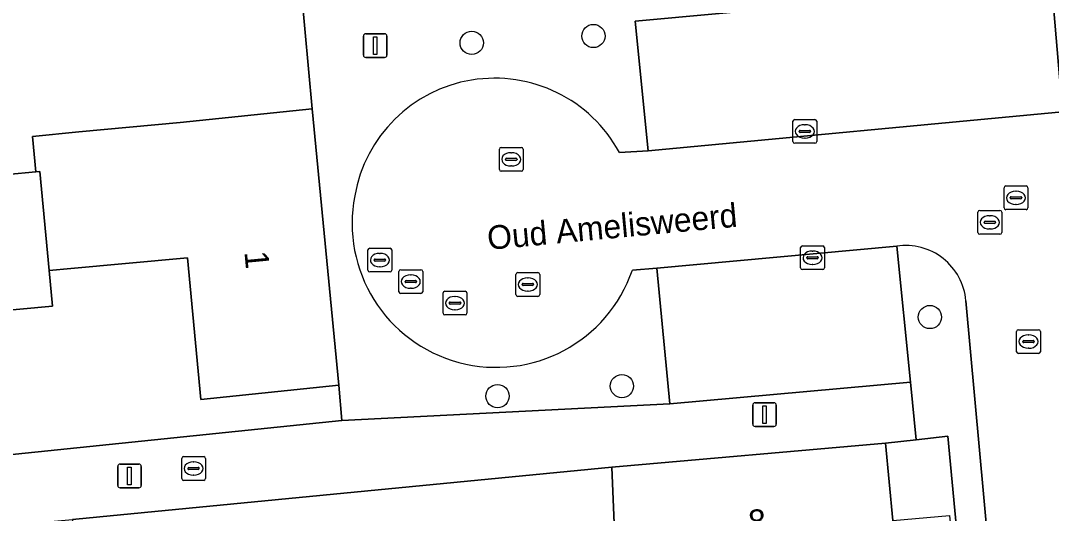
# Model space of a CAD drawing. Extents: x 157793 to 159380, y 380877 to 382313.
# Drawn here: x 158390.06 to 158433.42, y 381212.96 to 381233.72 of the extents above; entities that cross this region are included whole.
import ezdxf

# ---------------------------------------------------------------- set-up
doc = ezdxf.new("R2010")
doc.units = 0
for name, color, linetype in [('IMGEO_Boom', 7, 'Continuous'), ('IMGEO_Erf', 7, 'Continuous'), ('IMGEO_Kolk', 7, 'Continuous'), ('IMGEO_Lichtmast', 7, 'Continuous'), ('IMGEO_Openbare_ruimte_label', 7, 'Continuous'), ('IMGEO_Pand', 7, 'Continuous'), ('IMGEO_Pand_nummerreeks', 7, 'Continuous'), ('IMGEO_Parkeervlak_open', 7, 'Continuous'), ('IMGEO_Rijbaan_lokaal_open', 7, 'Continuous'), ('IMGEO_Rioolput', 7, 'Continuous'), ('IMGEO_Voetpad_open', 7, 'Continuous')]:
    doc.layers.add(name, color=color, linetype=linetype)

msp = doc.modelspace()

# ---------------------------------------------------------------- linework, layer by layer
at = {"layer": 'IMGEO_Boom'}
for centre in [(158414.154, 381233.068), (158409.036, 381232.779), (158428.309, 381221.233), (158415.353, 381218.326), (158410.121, 381217.902)]:
    msp.add_circle(centre, 0.489, dxfattribs=at)
at = {"layer": 'IMGEO_Erf'}
msp.add_lwpolyline([(158383.543, 381226.677), (158390.701, 381227.35), (158390.56, 381228.843), (158392.511, 381229.026), (158396.772, 381229.427), (158402.322, 381229.995), (158401.867, 381235.072), (158409.933, 381235.822), (158434.485, 381238.106)], dxfattribs=at)
for points in [[(158391.263, 381223.189), (158391.401, 381221.697), (158385.588, 381221.157), (158386.141, 381215.192), (158386.294, 381215.09), (158403.568, 381216.879), (158403.446, 381218.363), (158397.636, 381217.766), (158397.081, 381223.729), (158392.024, 381223.26), (158391.414, 381223.203)], [(158426.971, 381210.23), (158420.985, 381209.671), (158421.515, 381203.992), (158430.122, 381204.888), (158429.061, 381216.213), (158427.728, 381216.063), (158426.439, 381215.918), (158426.744, 381212.658), (158429.138, 381212.882), (158429.457, 381209.47), (158427.063, 381209.246)], [(158414.936, 381214.906), (158392.379, 381212.725), (158392.251, 381212.713), (158392.373, 381211.219), (158392.521, 381211.233), (158394.742, 381211.443), (158403.775, 381212.297), (158403.911, 381210.806), (158405.635, 381210.969), (158415.056, 381211.859)]]:
    msp.add_lwpolyline(points, close=True, dxfattribs=at)
at = {"layer": 'IMGEO_Kolk'}
for p, q in [((158422.621, 381229.552), (158423.473, 381229.552)), ((158422.546, 381228.626), (158422.546, 381229.478)), ((158423.034, 381229.332), (158423.059, 381229.332)), ((158423.547, 381229.478), (158423.547, 381228.626)), ((158422.805, 381229.046), (158422.805, 381229.058)), ((158423.243, 381229.009), (158422.845, 381229.009)), ((158422.848, 381229.095), (158423.246, 381229.095)), ((158423.057, 381228.772), (158423.032, 381228.772)), ((158423.289, 381229.058), (158423.289, 381229.046)), ((158410.199, 381227.448), (158410.199, 381228.3)), ((158410.274, 381228.374), (158411.126, 381228.374)), ((158411.2, 381228.3), (158411.2, 381227.448)), ((158423.473, 381228.552), (158422.621, 381228.552)), ((158410.458, 381227.868), (158410.458, 381227.88)), ((158410.896, 381227.831), (158410.498, 381227.831)), ((158410.501, 381227.917), (158410.899, 381227.917)), ((158410.687, 381228.154), (158410.712, 381228.154)), ((158410.942, 381227.88), (158410.942, 381227.868)), ((158410.71, 381227.594), (158410.685, 381227.594)), ((158411.126, 381227.374), (158410.274, 381227.374)), ((158422.871, 381223.305), (158422.871, 381224.157)), ((158422.946, 381224.231), (158423.798, 381224.231)), ((158423.359, 381224.011), (158423.384, 381224.011)), ((158423.872, 381224.157), (158423.872, 381223.305)), ((158423.13, 381223.725), (158423.13, 381223.737)), ((158423.568, 381223.688), (158423.17, 381223.688)), ((158423.173, 381223.774), (158423.571, 381223.774)), ((158423.614, 381223.737), (158423.614, 381223.725)), ((158410.972, 381223.105), (158411.824, 381223.105)), ((158423.798, 381223.231), (158422.946, 381223.231)), ((158423.382, 381223.451), (158423.357, 381223.451)), ((158410.897, 381222.179), (158410.897, 381223.031)), ((158411.199, 381222.648), (158411.597, 381222.648)), ((158411.385, 381222.885), (158411.41, 381222.885)), ((158411.898, 381223.031), (158411.898, 381222.179)), ((158411.156, 381222.599), (158411.156, 381222.611)), ((158411.594, 381222.562), (158411.196, 381222.562)), ((158411.408, 381222.325), (158411.383, 381222.325)), ((158411.64, 381222.611), (158411.64, 381222.599)), ((158411.824, 381222.105), (158410.972, 381222.105)), ((158431.955, 381219.773), (158431.955, 381220.625)), ((158432.03, 381220.699), (158432.882, 381220.699)), ((158432.443, 381220.479), (158432.468, 381220.479)), ((158432.956, 381220.625), (158432.956, 381219.773)), ((158432.214, 381220.193), (158432.214, 381220.205)), ((158432.652, 381220.156), (158432.254, 381220.156)), ((158432.257, 381220.242), (158432.655, 381220.242)), ((158432.698, 381220.205), (158432.698, 381220.193)), ((158432.882, 381219.699), (158432.03, 381219.699)), ((158432.466, 381219.919), (158432.441, 381219.919)), ((158396.837, 381214.428), (158396.837, 381215.28)), ((158396.912, 381215.354), (158397.764, 381215.354)), ((158397.838, 381215.28), (158397.838, 381214.428)), ((158397.096, 381214.848), (158397.096, 381214.86)), ((158397.139, 381214.897), (158397.537, 381214.897)), ((158397.325, 381215.134), (158397.35, 381215.134)), ((158397.58, 381214.86), (158397.58, 381214.848)), ((158397.534, 381214.811), (158397.136, 381214.811)), ((158397.348, 381214.574), (158397.323, 381214.574)), ((158397.764, 381214.354), (158396.912, 381214.354))]:
    msp.add_line(p, q, dxfattribs=at)
for points in [[(158422.621, 381229.552), (158423.473, 381229.552)], [(158422.546, 381228.626), (158422.546, 381229.478)], [(158423.547, 381229.478), (158423.547, 381228.626)], [(158410.199, 381227.448), (158410.199, 381228.3)], [(158410.274, 381228.374), (158411.126, 381228.374)], [(158411.2, 381228.3), (158411.2, 381227.448)], [(158423.473, 381228.552), (158422.621, 381228.552)], [(158411.126, 381227.374), (158410.274, 381227.374)], [(158422.871, 381223.305), (158422.871, 381224.157)], [(158422.946, 381224.231), (158423.798, 381224.231)], [(158423.872, 381224.157), (158423.872, 381223.305)], [(158410.972, 381223.105), (158411.824, 381223.105)], [(158423.798, 381223.231), (158422.946, 381223.231)], [(158410.897, 381222.179), (158410.897, 381223.031)], [(158411.898, 381223.031), (158411.898, 381222.179)], [(158411.824, 381222.105), (158410.972, 381222.105)], [(158431.955, 381219.773), (158431.955, 381220.625)], [(158432.03, 381220.699), (158432.882, 381220.699)], [(158432.956, 381220.625), (158432.956, 381219.773)], [(158432.882, 381219.699), (158432.03, 381219.699)], [(158396.837, 381214.428), (158396.837, 381215.28)], [(158396.912, 381215.354), (158397.764, 381215.354)], [(158397.838, 381215.28), (158397.838, 381214.428)], [(158397.764, 381214.354), (158396.912, 381214.354)]]:
    msp.add_lwpolyline(points, dxfattribs=at)
for centre, radius, start, end in [((158422.623, 381229.476), 0.0765, 91.552, 178.448), ((158422.623, 381229.476), 0.0765, 91.552, 178.448), ((158423.471, 381229.476), 0.0765, 1.552, 88.448), ((158423.471, 381229.476), 0.0765, 1.552, 88.448), ((158422.845, 381229.055), 0.0403, 85.8775, 175.7526), ((158422.842, 381229.045), 0.0366, 178.938, 274.7102), ((158423.246, 381229.052), 0.043, 264.8664, 352.4533), ((158423.25, 381229.057), 0.0386, 1.7309, 96.639), ((158410.276, 381228.298), 0.0765, 91.552, 178.448), ((158410.276, 381228.298), 0.0765, 91.552, 178.448), ((158411.124, 381228.298), 0.0765, 1.552, 88.448), ((158411.124, 381228.298), 0.0765, 1.552, 88.448), ((158422.623, 381228.628), 0.0765, 181.552, 268.448), ((158422.623, 381228.628), 0.0765, 181.552, 268.448), ((158423.471, 381228.628), 0.0765, 271.552, 358.448), ((158423.471, 381228.628), 0.0765, 271.552, 358.448), ((158410.498, 381227.877), 0.0403, 85.8775, 175.7526), ((158410.495, 381227.867), 0.0366, 178.938, 274.7102), ((158410.899, 381227.874), 0.043, 264.8664, 352.4533), ((158410.903, 381227.879), 0.0386, 1.7309, 96.639), ((158410.276, 381227.45), 0.0765, 181.552, 268.448), ((158410.276, 381227.45), 0.0765, 181.552, 268.448), ((158411.124, 381227.45), 0.0765, 271.552, 358.448), ((158411.124, 381227.45), 0.0765, 271.552, 358.448), ((158422.948, 381224.155), 0.0765, 91.552, 178.448), ((158422.948, 381224.155), 0.0765, 91.552, 178.448), ((158423.796, 381224.155), 0.0765, 1.552, 88.448), ((158423.796, 381224.155), 0.0765, 1.552, 88.448), ((158423.17, 381223.734), 0.0403, 85.8775, 175.7526), ((158423.167, 381223.724), 0.0366, 178.938, 274.7102), ((158423.571, 381223.731), 0.043, 264.8664, 352.4533), ((158423.575, 381223.736), 0.0386, 1.7309, 96.639), ((158410.974, 381223.029), 0.0765, 91.552, 178.448), ((158410.974, 381223.029), 0.0765, 91.552, 178.448), ((158411.822, 381223.029), 0.0765, 1.552, 88.448), ((158411.822, 381223.029), 0.0765, 1.552, 88.448), ((158422.948, 381223.307), 0.0765, 181.552, 268.448), ((158422.948, 381223.307), 0.0765, 181.552, 268.448), ((158423.796, 381223.307), 0.0765, 271.552, 358.448), ((158423.796, 381223.307), 0.0765, 271.552, 358.448), ((158411.196, 381222.608), 0.0403, 85.8775, 175.7526), ((158411.601, 381222.61), 0.0386, 1.7309, 96.639), ((158411.193, 381222.598), 0.0366, 178.938, 274.7102), ((158411.597, 381222.605), 0.043, 264.8664, 352.4533), ((158410.974, 381222.181), 0.0765, 181.552, 268.448), ((158410.974, 381222.181), 0.0765, 181.552, 268.448), ((158411.822, 381222.181), 0.0765, 271.552, 358.448), ((158411.822, 381222.181), 0.0765, 271.552, 358.448), ((158432.032, 381220.623), 0.0765, 91.552, 178.448), ((158432.032, 381220.623), 0.0765, 91.552, 178.448), ((158432.88, 381220.623), 0.0765, 1.552, 88.448), ((158432.88, 381220.623), 0.0765, 1.552, 88.448), ((158432.254, 381220.202), 0.0403, 85.8775, 175.7526), ((158432.251, 381220.192), 0.0366, 178.938, 274.7102), ((158432.655, 381220.199), 0.043, 264.8664, 352.4533), ((158432.659, 381220.204), 0.0386, 1.7309, 96.639), ((158432.032, 381219.775), 0.0765, 181.552, 268.448), ((158432.032, 381219.775), 0.0765, 181.552, 268.448), ((158432.88, 381219.775), 0.0765, 271.552, 358.448), ((158432.88, 381219.775), 0.0765, 271.552, 358.448), ((158396.914, 381215.278), 0.0765, 91.552, 178.448), ((158396.914, 381215.278), 0.0765, 91.552, 178.448), ((158397.762, 381215.278), 0.0765, 1.552, 88.448), ((158397.762, 381215.278), 0.0765, 1.552, 88.448), ((158397.136, 381214.857), 0.0403, 85.8775, 175.7526), ((158397.133, 381214.847), 0.0366, 178.938, 274.7102), ((158397.537, 381214.854), 0.043, 264.8664, 352.4533), ((158397.541, 381214.859), 0.0386, 1.7309, 96.639), ((158396.914, 381214.43), 0.0765, 181.552, 268.448), ((158396.914, 381214.43), 0.0765, 181.552, 268.448), ((158397.762, 381214.43), 0.0765, 271.552, 358.448), ((158397.762, 381214.43), 0.0765, 271.552, 358.448)]:
    msp.add_arc(centre, radius, start, end, dxfattribs=at)
for centre, major_axis, ratio, start_param, end_param in [((158423.033, 381229.052), (-0.387, 0.002), 0.722429, 4.712389, 7.853982), ((158423.058, 381229.052), (-0.39, 0.002), 0.717154, 1.570796, 4.712389), ((158410.686, 381227.874), (-0.387, 0.002), 0.722429, 4.712389, 7.853982), ((158410.711, 381227.874), (-0.39, 0.002), 0.717154, 1.570796, 4.712389), ((158423.358, 381223.731), (-0.387, 0.002), 0.722429, 4.712389, 7.853982), ((158423.383, 381223.731), (-0.39, 0.002), 0.717154, 1.570796, 4.712389), ((158411.384, 381222.605), (-0.387, 0.002), 0.722429, 4.712389, 7.853982), ((158411.409, 381222.605), (-0.39, 0.002), 0.717154, 1.570796, 4.712389), ((158432.442, 381220.199), (-0.387, 0.002), 0.722429, 4.712389, 7.853982), ((158432.467, 381220.199), (-0.39, 0.002), 0.717154, 1.570796, 4.712389), ((158397.324, 381214.854), (-0.387, 0.002), 0.722429, 4.712389, 7.853982), ((158397.349, 381214.854), (-0.39, 0.002), 0.717154, 1.570796, 4.712389)]:
    msp.add_ellipse(centre, major_axis=major_axis, ratio=ratio, start_param=start_param, end_param=end_param, dxfattribs=at)
at = {"layer": 'IMGEO_Lichtmast'}
for p, q in [((158404.48, 381232.264), (158404.48, 381233.064)), ((158404.48, 381233.064), (158404.48, 381232.264)), ((158404.58, 381233.164), (158405.37, 381233.164)), ((158405.37, 381233.164), (158404.58, 381233.164)), ((158405.47, 381233.064), (158405.47, 381232.264)), ((158405.47, 381232.264), (158405.47, 381233.064)), ((158405.37, 381232.164), (158404.58, 381232.164)), ((158404.58, 381232.164), (158405.37, 381232.164)), ((158420.856, 381216.724), (158420.856, 381217.524)), ((158420.856, 381217.524), (158420.856, 381216.724)), ((158420.956, 381217.624), (158421.746, 381217.624)), ((158421.746, 381217.624), (158420.956, 381217.624)), ((158421.846, 381217.524), (158421.846, 381216.724)), ((158421.846, 381216.724), (158421.846, 381217.524)), ((158421.746, 381216.624), (158420.956, 381216.624)), ((158420.956, 381216.624), (158421.746, 381216.624)), ((158394.145, 381214.14), (158394.145, 381214.94)), ((158394.145, 381214.94), (158394.145, 381214.14)), ((158394.245, 381215.04), (158395.035, 381215.04)), ((158395.035, 381215.04), (158394.245, 381215.04)), ((158395.135, 381214.94), (158395.135, 381214.14)), ((158395.135, 381214.14), (158395.135, 381214.94)), ((158395.035, 381214.04), (158394.245, 381214.04)), ((158394.245, 381214.04), (158395.035, 381214.04))]:
    msp.add_line(p, q, dxfattribs=at)
for points in [[(158404.9, 381233.039), (158405.05, 381233.039), (158405.05, 381232.289), (158404.9, 381232.289), (158404.9, 381233.039)], [(158421.276, 381217.499), (158421.426, 381217.499), (158421.426, 381216.749), (158421.276, 381216.749), (158421.276, 381217.499)], [(158394.565, 381214.915), (158394.715, 381214.915), (158394.715, 381214.165), (158394.565, 381214.165), (158394.565, 381214.915)]]:
    msp.add_lwpolyline(points, dxfattribs=at)
for centre, start, end in [((158404.58, 381233.064), 90, 180), ((158404.58, 381233.064), 90, 180), ((158405.37, 381233.064), 0, 90), ((158405.37, 381233.064), 360, 90), ((158404.58, 381232.264), 180, 270), ((158404.58, 381232.264), 180, 270), ((158405.37, 381232.264), 270, 0), ((158405.37, 381232.264), 270, 0), ((158420.956, 381217.524), 90, 180), ((158420.956, 381217.524), 90, 180), ((158421.746, 381217.524), 0, 90), ((158421.746, 381217.524), 360, 90), ((158420.956, 381216.724), 180, 270), ((158420.956, 381216.724), 180, 270), ((158421.746, 381216.724), 270, 0), ((158421.746, 381216.724), 270, 0), ((158394.245, 381214.94), 90, 180), ((158394.245, 381214.94), 90, 180), ((158395.035, 381214.94), 0, 90), ((158395.035, 381214.94), 360, 90), ((158394.245, 381214.14), 180, 270), ((158394.245, 381214.14), 180, 270), ((158395.035, 381214.14), 270, 0), ((158395.035, 381214.14), 270, 0)]:
    msp.add_arc(centre, 0.1, start, end, dxfattribs=at)
at = {"layer": 'IMGEO_Pand'}
for points in [[(158402.322, 381229.995), (158396.772, 381229.427), (158392.511, 381229.026), (158390.56, 381228.843), (158390.701, 381227.35), (158390.876, 381227.366), (158391.263, 381223.189), (158391.414, 381223.203), (158392.024, 381223.26), (158397.081, 381223.729), (158397.636, 381217.766), (158403.446, 381218.363)], [(158390.701, 381227.35), (158383.543, 381226.677), (158383.555, 381226.549), (158379.381, 381226.167), (158379.397, 381225.995), (158379.573, 381224.131), (158380.47, 381214.66), (158386.141, 381215.192), (158385.588, 381221.157), (158391.401, 381221.697), (158391.263, 381223.189), (158390.876, 381227.366)], [(158426.971, 381210.23), (158426.744, 381212.658), (158426.439, 381215.918), (158414.936, 381214.906), (158415.056, 381211.859), (158416.047, 381203.193), (158416.207, 381203.208), (158418.385, 381203.408), (158418.369, 381203.587), (158421.525, 381203.881), (158421.515, 381203.992), (158420.985, 381209.671)]]:
    msp.add_lwpolyline(points, close=True, dxfattribs=at)
at = {"layer": 'IMGEO_Parkeervlak_open'}
for points in [[(158434.025, 381229.887), (158433.976, 381230.217), (158433.857, 381230.192), (158433.421, 381235.303), (158415.915, 381233.688), (158416.46, 381228.231)], [(158427.485, 381218.497), (158426.913, 381224.222), (158416.824, 381223.289), (158417.373, 381217.577)]]:
    msp.add_lwpolyline(points, close=True, dxfattribs=at)
at = {"layer": 'IMGEO_Rijbaan_lokaal_open'}
for points in [[(158434.025, 381229.887), (158416.46, 381228.231), (158415.248, 381228.166)], [(158429.819, 381221.92), (158431.533, 381203.205), (158436.443, 381203.658), (158434.025, 381229.887)], [(158415.796, 381223.213), (158416.824, 381223.289), (158426.913, 381224.222)]]:
    msp.add_lwpolyline(points, dxfattribs=at)
for centre, radius, start, end in [((158410, 381225.322), 5.969, 28.4562, 170.1794), ((158410.064, 381225.173), 6.058, 168.8941, 341.1228), ((158427.283, 381221.703), 2.546, 4.8817, 98.3489)]:
    msp.add_arc(centre, radius, start, end, dxfattribs=at)
at = {"layer": 'IMGEO_Rioolput'}
for p, q in [((158431.427, 381225.829), (158431.427, 381226.681)), ((158431.502, 381226.755), (158432.354, 381226.755)), ((158431.915, 381226.535), (158431.94, 381226.535)), ((158432.428, 381226.681), (158432.428, 381225.829)), ((158431.686, 381226.249), (158431.686, 381226.261)), ((158432.124, 381226.212), (158431.726, 381226.212)), ((158431.729, 381226.298), (158432.127, 381226.298)), ((158432.17, 381226.261), (158432.17, 381226.249)), ((158430.403, 381225.721), (158431.255, 381225.721)), ((158432.354, 381225.755), (158431.502, 381225.755)), ((158431.938, 381225.975), (158431.913, 381225.975)), ((158430.328, 381224.795), (158430.328, 381225.647)), ((158430.587, 381225.215), (158430.587, 381225.227)), ((158430.63, 381225.264), (158431.028, 381225.264)), ((158430.816, 381225.501), (158430.841, 381225.501)), ((158431.071, 381225.227), (158431.071, 381225.215)), ((158431.329, 381225.647), (158431.329, 381224.795)), ((158431.025, 381225.178), (158430.627, 381225.178)), ((158430.839, 381224.941), (158430.814, 381224.941)), ((158431.255, 381224.721), (158430.403, 381224.721)), ((158404.673, 381223.207), (158404.673, 381224.059)), ((158404.748, 381224.133), (158405.6, 381224.133)), ((158405.674, 381224.059), (158405.674, 381223.207)), ((158404.932, 381223.627), (158404.932, 381223.639)), ((158405.37, 381223.59), (158404.972, 381223.59)), ((158404.975, 381223.676), (158405.373, 381223.676)), ((158405.161, 381223.913), (158405.186, 381223.913)), ((158405.416, 381223.639), (158405.416, 381223.627)), ((158405.6, 381223.133), (158404.748, 381223.133)), ((158405.184, 381223.353), (158405.159, 381223.353)), ((158405.973, 381222.298), (158405.973, 381223.15)), ((158406.048, 381223.224), (158406.9, 381223.224)), ((158406.974, 381223.15), (158406.974, 381222.298)), ((158406.232, 381222.718), (158406.232, 381222.73)), ((158406.67, 381222.681), (158406.272, 381222.681)), ((158406.275, 381222.767), (158406.673, 381222.767)), ((158406.461, 381223.004), (158406.486, 381223.004)), ((158406.716, 381222.73), (158406.716, 381222.718)), ((158406.9, 381222.224), (158406.048, 381222.224)), ((158406.484, 381222.444), (158406.459, 381222.444)), ((158407.833, 381221.394), (158407.833, 381222.246)), ((158407.908, 381222.32), (158408.76, 381222.32)), ((158408.834, 381222.246), (158408.834, 381221.394)), ((158408.092, 381221.814), (158408.092, 381221.826)), ((158408.53, 381221.777), (158408.132, 381221.777)), ((158408.135, 381221.863), (158408.533, 381221.863)), ((158408.321, 381222.1), (158408.346, 381222.1)), ((158408.576, 381221.826), (158408.576, 381221.814)), ((158408.76, 381221.32), (158407.908, 381221.32)), ((158408.344, 381221.54), (158408.319, 381221.54))]:
    msp.add_line(p, q, dxfattribs=at)
for points in [[(158431.427, 381225.829), (158431.427, 381226.681)], [(158431.502, 381226.755), (158432.354, 381226.755)], [(158432.428, 381226.681), (158432.428, 381225.829)], [(158430.403, 381225.721), (158431.255, 381225.721)], [(158432.354, 381225.755), (158431.502, 381225.755)], [(158430.328, 381224.795), (158430.328, 381225.647)], [(158431.329, 381225.647), (158431.329, 381224.795)], [(158431.255, 381224.721), (158430.403, 381224.721)], [(158404.673, 381223.207), (158404.673, 381224.059)], [(158404.748, 381224.133), (158405.6, 381224.133)], [(158405.674, 381224.059), (158405.674, 381223.207)], [(158405.6, 381223.133), (158404.748, 381223.133)], [(158405.973, 381222.298), (158405.973, 381223.15)], [(158406.048, 381223.224), (158406.9, 381223.224)], [(158406.974, 381223.15), (158406.974, 381222.298)], [(158406.9, 381222.224), (158406.048, 381222.224)], [(158407.833, 381221.394), (158407.833, 381222.246)], [(158407.908, 381222.32), (158408.76, 381222.32)], [(158408.834, 381222.246), (158408.834, 381221.394)], [(158408.76, 381221.32), (158407.908, 381221.32)]]:
    msp.add_lwpolyline(points, dxfattribs=at)
for centre, radius, start, end in [((158431.504, 381226.679), 0.0765, 91.552, 178.448), ((158431.504, 381226.679), 0.0765, 91.552, 178.448), ((158432.352, 381226.679), 0.0765, 1.552, 88.448), ((158432.352, 381226.679), 0.0765, 1.552, 88.448), ((158431.726, 381226.258), 0.0403, 85.8775, 175.7526), ((158431.723, 381226.248), 0.0366, 178.938, 274.7102), ((158432.127, 381226.255), 0.043, 264.8664, 352.4533), ((158432.131, 381226.26), 0.0386, 1.7309, 96.639), ((158430.405, 381225.645), 0.0765, 91.552, 178.448), ((158430.405, 381225.645), 0.0765, 91.552, 178.448), ((158431.253, 381225.645), 0.0765, 1.552, 88.448), ((158431.253, 381225.645), 0.0765, 1.552, 88.448), ((158431.504, 381225.831), 0.0765, 181.552, 268.448), ((158431.504, 381225.831), 0.0765, 181.552, 268.448), ((158432.352, 381225.831), 0.0765, 271.552, 358.448), ((158432.352, 381225.831), 0.0765, 271.552, 358.448), ((158430.627, 381225.224), 0.0403, 85.8775, 175.7526), ((158431.032, 381225.226), 0.0386, 1.7309, 96.639), ((158430.405, 381224.797), 0.0765, 181.552, 268.448), ((158430.405, 381224.797), 0.0765, 181.552, 268.448), ((158430.624, 381225.214), 0.0366, 178.938, 274.7102), ((158431.028, 381225.221), 0.043, 264.8664, 352.4533), ((158431.253, 381224.797), 0.0765, 271.552, 358.448), ((158431.253, 381224.797), 0.0765, 271.552, 358.448), ((158404.75, 381224.057), 0.0765, 91.552, 178.448), ((158404.75, 381224.057), 0.0765, 91.552, 178.448), ((158405.598, 381224.057), 0.0765, 1.552, 88.448), ((158405.598, 381224.057), 0.0765, 1.552, 88.448), ((158404.972, 381223.636), 0.0403, 85.8775, 175.7526), ((158404.969, 381223.626), 0.0366, 178.938, 274.7102), ((158405.373, 381223.633), 0.043, 264.8664, 352.4533), ((158405.377, 381223.638), 0.0386, 1.7309, 96.639), ((158404.75, 381223.209), 0.0765, 181.552, 268.448), ((158404.75, 381223.209), 0.0765, 181.552, 268.448), ((158405.598, 381223.209), 0.0765, 271.552, 358.448), ((158405.598, 381223.209), 0.0765, 271.552, 358.448), ((158406.05, 381223.148), 0.0765, 91.552, 178.448), ((158406.05, 381223.148), 0.0765, 91.552, 178.448), ((158406.898, 381223.148), 0.0765, 1.552, 88.448), ((158406.898, 381223.148), 0.0765, 1.552, 88.448), ((158406.272, 381222.727), 0.0403, 85.8775, 175.7526), ((158406.269, 381222.717), 0.0366, 178.938, 274.7102), ((158406.673, 381222.724), 0.043, 264.8664, 352.4533), ((158406.677, 381222.729), 0.0386, 1.7309, 96.639), ((158406.05, 381222.3), 0.0765, 181.552, 268.448), ((158406.05, 381222.3), 0.0765, 181.552, 268.448), ((158406.898, 381222.3), 0.0765, 271.552, 358.448), ((158406.898, 381222.3), 0.0765, 271.552, 358.448), ((158407.91, 381222.244), 0.0765, 91.552, 178.448), ((158407.91, 381222.244), 0.0765, 91.552, 178.448), ((158408.758, 381222.244), 0.0765, 1.552, 88.448), ((158408.758, 381222.244), 0.0765, 1.552, 88.448), ((158408.132, 381221.823), 0.0403, 85.8775, 175.7526), ((158408.129, 381221.813), 0.0366, 178.938, 274.7102), ((158408.533, 381221.82), 0.043, 264.8664, 352.4533), ((158408.537, 381221.825), 0.0386, 1.7309, 96.639), ((158407.91, 381221.396), 0.0765, 181.552, 268.448), ((158407.91, 381221.396), 0.0765, 181.552, 268.448), ((158408.758, 381221.396), 0.0765, 271.552, 358.448), ((158408.758, 381221.396), 0.0765, 271.552, 358.448)]:
    msp.add_arc(centre, radius, start, end, dxfattribs=at)
for centre, major_axis, ratio, start_param, end_param in [((158431.914, 381226.255), (-0.387, 0.002), 0.722429, 4.712389, 7.853982), ((158431.939, 381226.255), (-0.39, 0.002), 0.717154, 1.570796, 4.712389), ((158430.815, 381225.221), (-0.387, 0.002), 0.722429, 4.712389, 7.853982), ((158430.84, 381225.221), (-0.39, 0.002), 0.717154, 1.570796, 4.712389), ((158405.16, 381223.633), (-0.387, 0.002), 0.722429, 4.712389, 7.853982), ((158405.185, 381223.633), (-0.39, 0.002), 0.717154, 1.570796, 4.712389), ((158406.46, 381222.724), (-0.387, 0.002), 0.722429, 4.712389, 7.853982), ((158406.485, 381222.724), (-0.39, 0.002), 0.717154, 1.570796, 4.712389), ((158408.32, 381221.82), (-0.387, 0.002), 0.722429, 4.712389, 7.853982), ((158408.345, 381221.82), (-0.39, 0.002), 0.717154, 1.570796, 4.712389)]:
    msp.add_ellipse(centre, major_axis=major_axis, ratio=ratio, start_param=start_param, end_param=end_param, dxfattribs=at)
at = {"layer": 'IMGEO_Voetpad_open'}
for points in [[(158415.915, 381233.688), (158433.421, 381235.303), (158433.857, 381230.192), (158433.976, 381230.217), (158435.253, 381230.392), (158434.485, 381238.106), (158409.933, 381235.822), (158401.867, 381235.072), (158402.322, 381229.995), (158403.446, 381218.363), (158403.568, 381216.879), (158417.373, 381217.577), (158416.824, 381223.289), (158415.796, 381223.213)], [(158415.248, 381228.166), (158416.46, 381228.231), (158415.915, 381233.688)], [(158426.913, 381224.222), (158427.485, 381218.497), (158427.728, 381216.063), (158429.061, 381216.213), (158430.122, 381204.888), (158430.286, 381203.09), (158431.533, 381203.205), (158429.819, 381221.92)]]:
    msp.add_lwpolyline(points, dxfattribs=at)
msp.add_lwpolyline([(158414.936, 381214.906), (158426.439, 381215.918), (158427.728, 381216.063), (158427.485, 381218.497), (158417.373, 381217.577), (158403.568, 381216.879), (158386.294, 381215.09), (158386.141, 381215.192), (158380.47, 381214.66), (158377.638, 381214.267), (158377.877, 381211.408), (158380.748, 381211.65), (158392.251, 381212.713), (158392.379, 381212.725)], close=True, dxfattribs=at)
for centre, radius, start, end in [((158410, 381225.322), 5.969, 28.4562, 170.1794), ((158410.064, 381225.173), 6.058, 168.8941, 341.1228), ((158427.283, 381221.703), 2.546, 4.8817, 98.3489)]:
    msp.add_arc(centre, radius, start, end, dxfattribs=at)

# ---------------------------------------------------------------- texts
at = {"layer": 'IMGEO_Openbare_ruimte_label'}
msp.add_text('Oud Amelisweerd', height=1, rotation=5.3344, dxfattribs=at).set_placement((158409.735, 381224.06))
at = {"layer": 'IMGEO_Pand_nummerreeks'}
for s, rotation, p in [('1', 275.3741, (158399.475, 381223.969)), ('8', 5.2483, (158420.723, 381212.1))]:
    msp.add_text(s, height=1, rotation=rotation, dxfattribs=at).set_placement(p)

doc.saveas('drawing.dxf')
